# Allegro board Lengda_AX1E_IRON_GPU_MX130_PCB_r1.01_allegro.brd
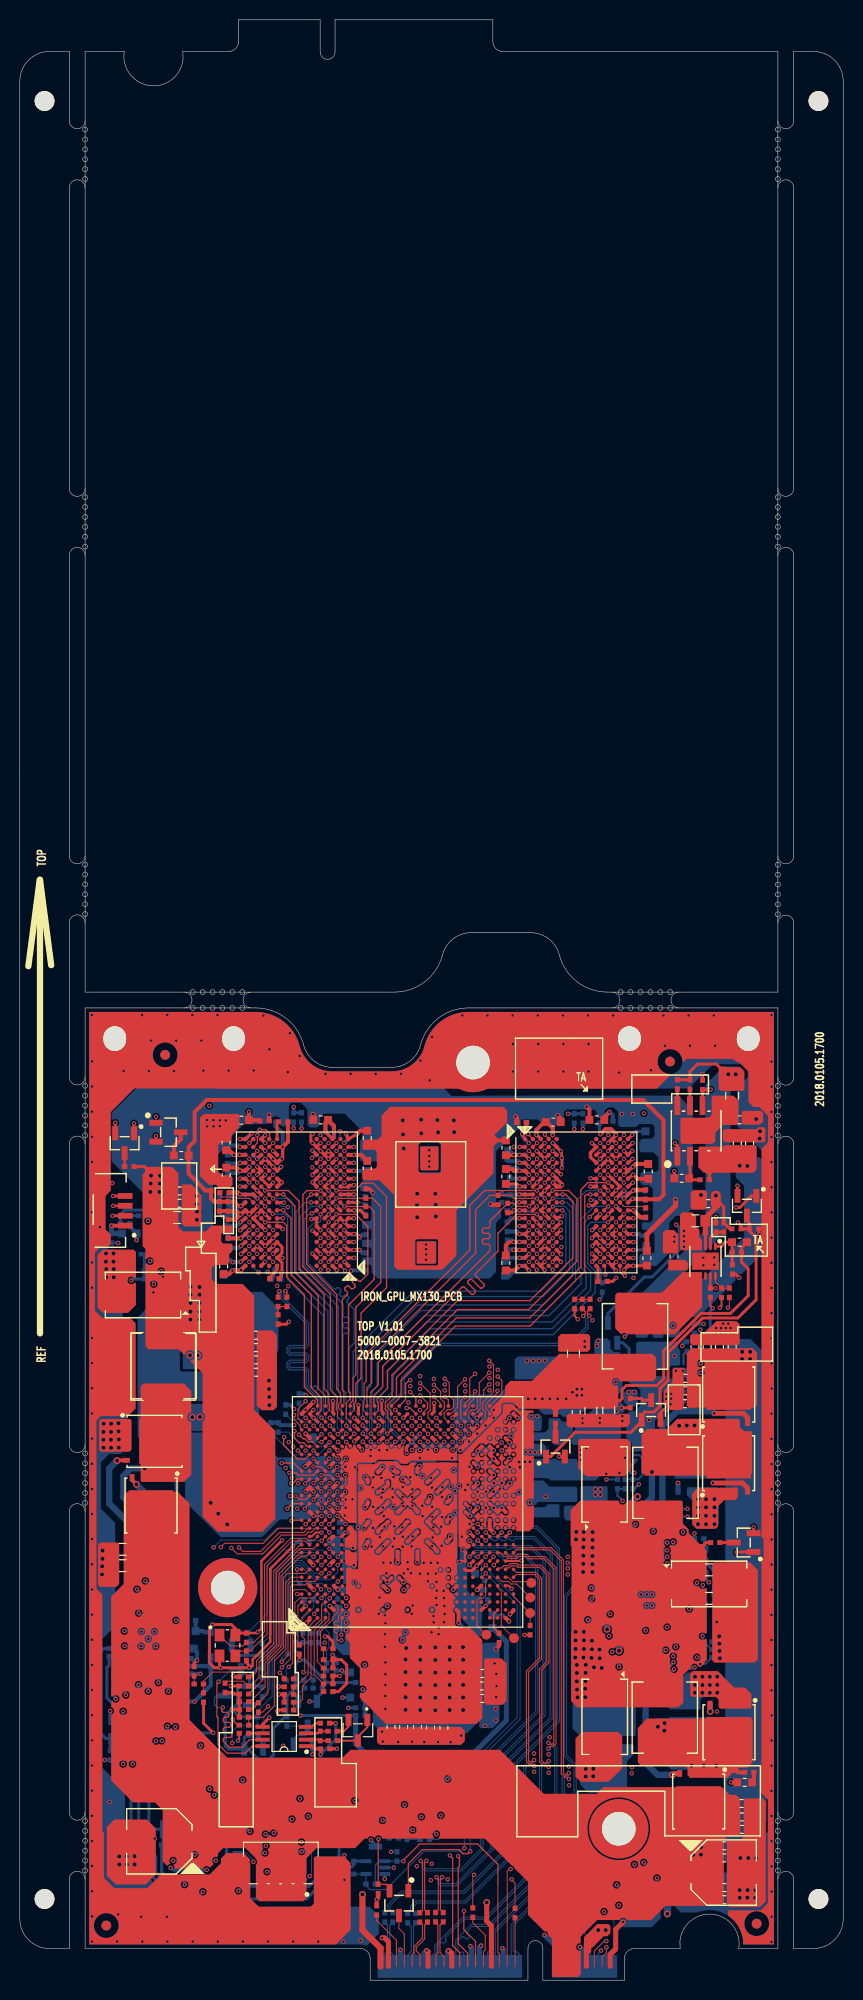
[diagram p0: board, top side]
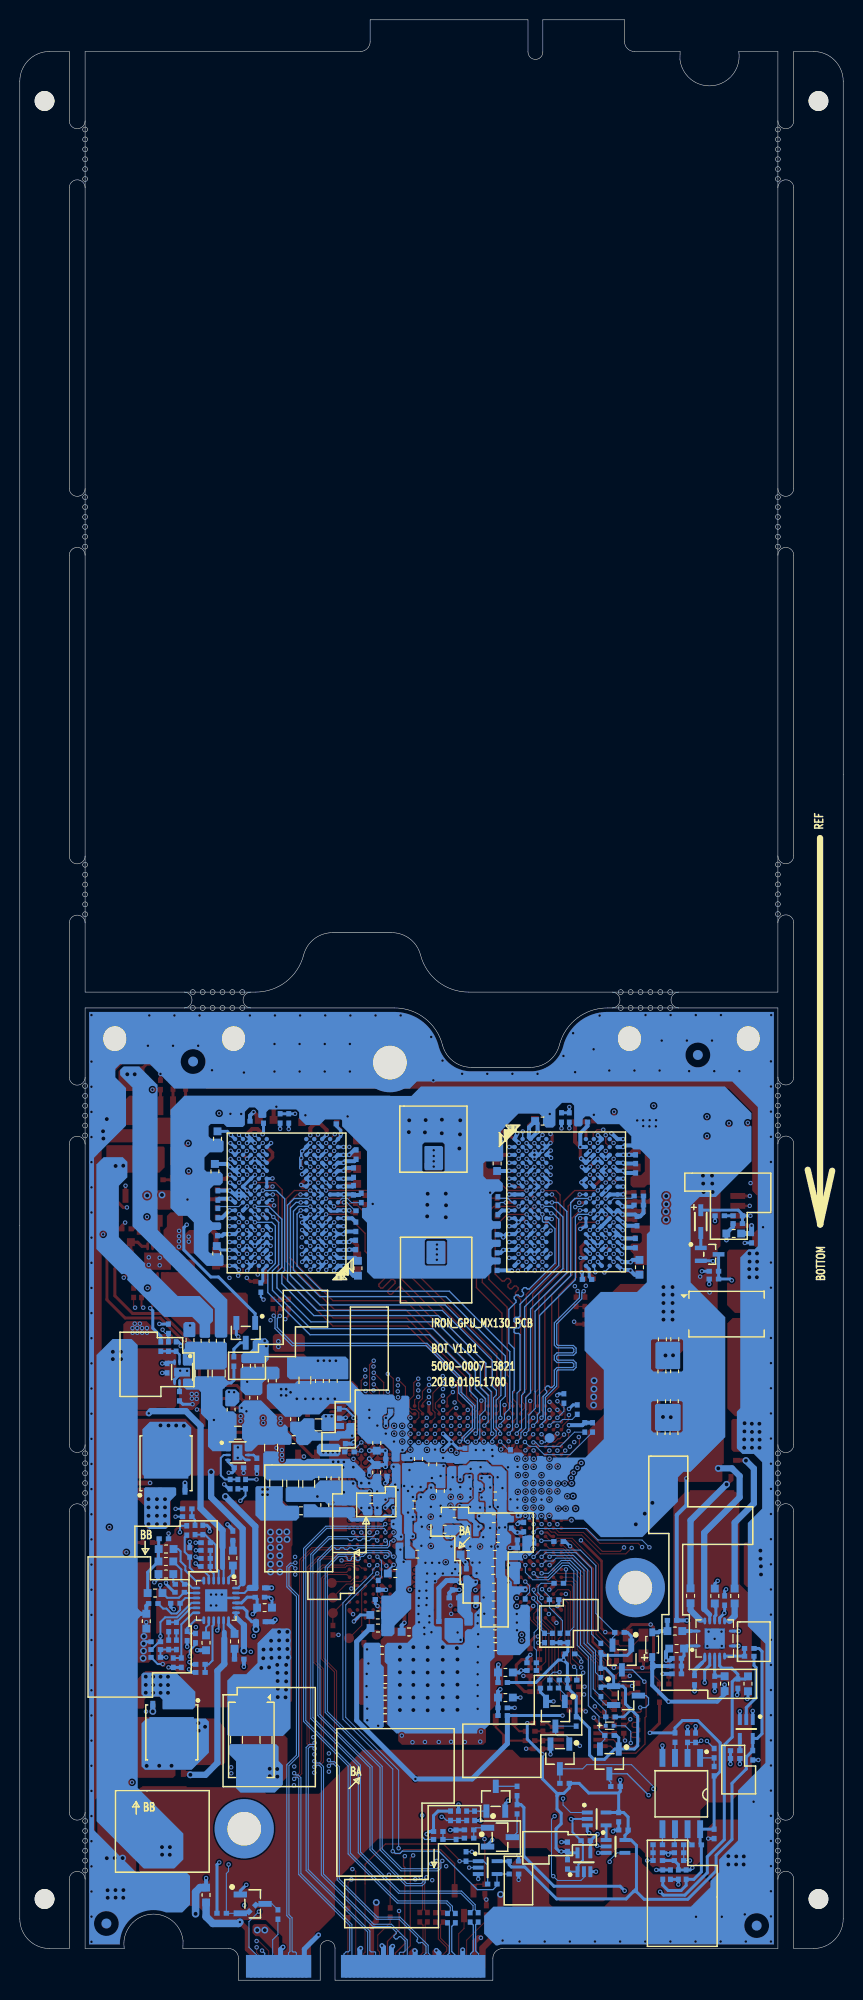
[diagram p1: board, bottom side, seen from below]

Outline 83.2 x 198 mm; copper layers: TOP, L2, L3, L4, L5, L6, L7, BOTTOM. Coordinates in mm from the lower left corner of the outline.

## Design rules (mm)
net group FBA_DQS<0>: nets FBA_DBI0 FBA_EDC0
net group FBA_DQS<1>: nets FBA_DBI1 FBA_EDC1
net group FBA_DQS<2>: nets FBA_DBI2 FBA_EDC2
net group FBA_DQS<3>: nets FBA_DBI3 FBA_EDC3
net group FBA_DQS<4>: nets FBA_DBI4 FBA_EDC4
net group FBA_DQS<5>: nets FBA_DBI5 FBA_EDC5
net group FBA_DQS<6>: nets FBA_DBI6 FBA_EDC6
net group FBA_DQS<7>: nets FBA_DBI7 FBA_EDC7
net group M_PCIE_TX3_GPU: nets PCIE_TXN3_GPU PCIE_TXP3_GPU
net group PCIE_RXN1_GPU: nets PCIE_RXN1_GPU PEX_TX0#
net group PCIE_RXN2_GPU: nets PCIE_RXN2_GPU PEX_TX1#
net group PCIE_RXN3_GPU: nets PCIE_RXN3_GPU PEX_TX2#
net group PCIE_RXN4_GPU: nets PCIE_RXN4_GPU PEX_TX3#
net group PCIE_RXP1_GPU: nets PCIE_RXP1_GPU PEX_TX0
net group PCIE_RXP2_GPU: nets PCIE_RXP2_GPU PEX_TX1
net group PCIE_RXP3_GPU: nets PCIE_RXP3_GPU PEX_TX2
net group PCIE_RXP4_GPU: nets PCIE_RXP4_GPU PEX_TX3
net group PEX_REFCLK: nets CLK_PCIE_GPU_N CLK_PCIE_GPU_P
net group PEX_RX0: nets PCIE_TXN1_GPU PCIE_TXP1_GPU
net group PEX_RX1: nets PCIE_TXN2_GPU PCIE_TXP4_GPU
net group FBA_DATA0: nets FBA_D0 FBA_D1 FBA_D2 FBA_D3 FBA_D4 FBA_D5 FBA_D6 FBA_D7
net group FBA_DATA1: nets FBA_D8 FBA_D9 FBA_D10 FBA_D11 FBA_D12 FBA_D13 FBA_D14 FBA_D15
net group FBA_DATA2: nets FBA_D16 FBA_D17 FBA_D18 FBA_D19 FBA_D20 FBA_D21 FBA_D22 FBA_D23
net group FBA_DATA3: nets FBA_D24 FBA_D25 FBA_D26 FBA_D27 FBA_D28 FBA_D29 FBA_D30 FBA_D31
net group FBA_DATA4: nets FBA_D32 FBA_D33 FBA_D34 FBA_D35 FBA_D36 FBA_D37 FBA_D38 FBA_D39
net group FBA_DATA5: nets FBA_D40 FBA_D41 FBA_D42 FBA_D43 FBA_D44 FBA_D45 FBA_D46 FBA_D47
net group FBA_DATA6: nets FBA_D48 FBA_D49 FBA_D50 FBA_D51 FBA_D52 FBA_D53 FBA_D54 FBA_D55
net group FBA_DATA7: nets FBA_D56 FBA_D57 FBA_D58 FBA_D59 FBA_D60 FBA_D61 FBA_D62 FBA_D63
net group M_PCIE_TX2_GPU: nets PCIE_TXP2_GPU
net group M_PCIE_TX4_GPU: nets PCIE_TXN4_GPU
net group NET_GND: nets GND
net group POWER: nets +V1P8S
nets with their own width: min track width 0.003; nets VDD_GPU_MAIN

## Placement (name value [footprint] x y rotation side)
C1  820pF  [CC0402N]  58.88 70.58 0 top
C2  1uF  [CC0402N]  49.63 47.76 90 bottom
C3  820pF  [CC0402N]  63.25 79.35 90 top
C4  820pF  [CC0402N]  25.89 70.78 0 bottom
C5  820pF  [CC0402N]  58.85 69.96 270 bottom
C6  820pF  [CC0402N]  20.66 78.29 180 bottom
C7  4.7uF  [CC0603N]  52.38 47.98 90 bottom
C8  0.01uF  [CC0402N]  56.06 68.29 270 top
C9  820pF  [CC0402N]  63.18 79.26 90 bottom
C10  100NF  [CC0402N]  50.41 47.75 90 bottom
C11  1uF  [CC0402N]  50.5 60.55 90 bottom
C12  10uF  [CC0603N]  73.74 84.53 90 top
C13  10uF  [CC0603N]  72.5 84.52 90 top
C14  1uF  [CC0402N]  45.74 52.64 0 bottom
C15  0.1u  [CC0402N]  71.5 84.47 90 top
C16  10uF  [CC0603N]  72.73 86.89 0 top
C17  0.1u  [CC0402N]  68.99 90.42 90 top
C18  100NF  [CC0402N]  30.86 23.38 0 top
C19  470pF  [CC0402N]  30.35 24.67 90 top
C20  1000pF  [CC0402N]  17.62 31.2 270 top
C21  100NF  [CC0402N]  33.27 12.02 0 bottom
C22  0.01uF  [CC0402N]  37.8 15.18 180 bottom
C23  0.01uF  [CC0402N]  37.25 16.61 90 bottom
C24  100NF  [CC0402N]  48.44 34.57 90 top
C275  1uF  [CC0402N]  46.21 57.48 180 bottom
C276  4.7uF  [CC0603N]  47.13 54.24 270 bottom
C298  4.7uF  [CC0603N]  56.22 57.39 270 top
C310  10UF  [CC0603N]  51.53 60.54 90 bottom
C322  10UF  [CC0603N]  52.93 60.51 90 bottom
C326  22uF  [CC0805N]  54.39 60.59 90 bottom
C327  22uF  [CC0805N]  55.94 63.28 90 top
C330  0.22uF  [CC0402N]  41.19 6.34 90 top
C331  0.22uF  [CC0402N]  40.42 6.34 90 top
C332  0.22uF  [CC0402N]  42.79 6.36 90 top
C333  0.22uF  [CC0402N]  42.01 6.36 90 top
C338  1uF  [CC0402N]  45.62 50.91 0 bottom
C342  1uF  [CC0402N]  44.46 46.37 180 bottom
C344  1uF  [CC0402N]  47.5 47.21 0 bottom
C370  1uF  [CC0402N]  45.61 48.84 270 bottom
C471  4.7uF  [CC0603N]  52.59 50.69 270 bottom
C472  4.7uF  [CC0603N]  51.34 50.69 270 bottom
C473  10UF  [CC0603N]  47.67 48.56 0 bottom
C474  10UF  [CC0603N]  47.14 51.28 90 bottom
C475  22uF  [CC0805N]  54.01 50.13 270 bottom
C476  22uF  [CC0805N]  55.62 50.16 270 bottom
C478  0.22uF  [CC0402N]  37.69 6.34 90 bottom
C532  0.22uF  [CC0402N]  36.88 6.34 90 bottom
C533  0.22uF  [CC0402N]  39.98 6.27 90 bottom
C534  0.22uF  [CC0402N]  39.19 6.27 90 bottom
C536  100NF  [CC0402N]  46.81 38.45 0 bottom
C537  4.7uF  [CC0603N]  47.03 36.89 0 bottom
C539  820pF  [CC0402N]  25.74 70.85 0 top
C540  820pF  [CC0402N]  26.62 86.7 0 top
C541  0.01uF  [CC0402N]  26.11 66.74 270 top
C542  820pF  [CC0402N]  21.04 78.15 270 top
C543  10uF  [CC0603N]  20.6 72.08 270 top
C553  1UF  [CC0402N]  42.25 73.49 180 bottom
C554  1UF  [CC0402N]  20.97 82.01 270 bottom
C555  1UF  [CC0402N]  20.98 83.84 270 bottom
C556  1UF  [CC0402N]  20.83 76.67 90 bottom
C557  100NF  [CC0402N]  21 74.45 90 bottom
C558  100NF  [CC0402N]  34.97 72.16 270 bottom
C559  100NF  [CC0402N]  26.31 86.68 180 bottom
C560  100NF  [CC0402N]  24.72 86.78 180 top
C561  100NF  [CC0402N]  58.57 87.03 270 bottom
C562  100NF  [CC0402N]  63.22 75.68 270 bottom
C567  100NF  [CC0402N]  50.3 55.96 0 bottom
C568  100NF  [CC0402N]  50.31 54.66 270 bottom
C569  22uF  [CC0805N]  53.02 56.09 180 bottom
C570  100NF  [CC0402N]  52.09 54.36 270 bottom
C571  100NF  [CC0402N]  51.28 54.35 270 bottom
C572  10uF  [CC0603N]  34.97 82.48 270 bottom
C573  1UF  [CC0402N]  42.23 74.27 180 top
C574  100NF  [CC0402N]  37.56 38.61 180 bottom
C575  1UF  [CC0402N]  21.05 76.35 90 top
C576  1UF  [CC0402N]  21.05 74.5 90 top
C577  1UF  [CC0402N]  42.23 73.5 180 top
C578  10uF  [CC0603N]  20.86 81.33 90 top
C579  1UF  [CC0402N]  49.48 81.57 90 bottom
C580  1UF  [CC0402N]  49.24 76.09 270 bottom
C581  1UF  [CC0402N]  49.26 74.26 270 bottom
C582  1UF  [CC0402N]  42.26 72.67 180 bottom
C583  100NF  [CC0402N]  34.96 73.94 270 bottom
C584  100NF  [CC0402N]  34.97 75.78 270 bottom
C585  100NF  [CC0402N]  42.23 72.71 180 top
C586  100NF  [CC0402N]  39.95 73.49 0 top
C587  100NF  [CC0402N]  39.95 74.3 0 top
C588  100NF  [CC0402N]  50.75 86.5 0 bottom
C596  10uF  [CC0603N]  20.84 84.59 270 top
C597  1UF  [CC0402N]  49.21 83.39 90 bottom
C598  1UF  [CC0402N]  40.06 72.66 0 bottom
C599  1UF  [CC0402N]  49.48 79.78 270 bottom
C600  1UF  [CC0402N]  42.23 74.29 180 bottom
C602  1UF  [CC0402N]  40.3 82.22 0 top
C603  1UF  [CC0402N]  33.91 47.82 0 bottom
C604  1UF  [CC0402N]  40.29 83.02 0 top
C605  10uF  [CC0603N]  30.38 86.77 0 bottom
C606  10uF  [CC0603N]  35.11 85.05 90 top
C607  22uF  [CC0603N]  18.27 64.73 270 bottom
C619  22uF  [CC0603N]  17.02 64.73 270 bottom
C620  100NF  [CC0402N]  38.22 53.26 90 bottom
C621  100NF  [CC0402N]  36.06 52.36 270 bottom
C622  1uF  [CC0603N]  35.11 82 90 top
C623  10uF  [CC0603N]  49.11 72.44 90 top
C624  1UF  [CC0402N]  33.97 50.28 0 bottom
C625  1UF  [CC0402N]  33.96 51.1 0 bottom
C628  1UF  [CC0402N]  35.25 51.98 270 bottom
C629  10uF  [CC0603N]  53.91 86.67 180 top
C630  10uF  [CC0603N]  49.12 84.08 90 top
C631  10uF  [CC0603N]  30.4 86.89 0 top
C632  22uF  [CC0603N]  42.91 52.64 270 bottom
C633  22uF  [CC0603N]  22.4 86.86 0 top
C634  100NF  [CC0402N]  37.23 52.58 270 bottom
C635  100NF  [CC0402N]  44.32 52.41 270 bottom
C636  1uF  [CC0603N]  20.59 72 270 bottom
C637  1UF  [CC0402N]  50.7 86.63 0 top
C638  1UF  [CC0402N]  40.28 83.85 0 top
C647  1UF  [CC0402N]  42.44 83.84 180 top
C670  10uF  [CC0603N]  41.47 52.1 270 bottom
C672  10uF  [CC0603N]  23.86 65.14 180 top
C681  10uF  [CC0603N]  58.3 86.89 0 top
C682  22uF  [CC0603N]  63.5 81.69 90 top
C683  22uF  [CC0603N]  63.37 72.93 270 top
C684  100NF  [CC0402N]  60.41 86.75 180 bottom
C691  100NF  [CC0402N]  42.45 83.05 180 top
C692  1uF  [CC0603N]  63.3 73.4 90 bottom
C707  1UF  [CC0402N]  39.94 72.7 0 top
C710  1UF  [CC0402N]  42.48 82.26 180 top
C715  1UF  [CC0402N]  23.77 59.52 0 top
C726  10uF  [CC0603N]  23.87 63.89 0 top
C729  10uF  [CC0603N]  23.87 62.65 0 top
C739  0.1uF  [CC0603N]  68.22 63.97 90 top
C741  22uF  [CC0603N]  63.48 81.69 90 bottom
C742  22uF  [CC0603N]  63.22 84.98 90 bottom
C743  100NF  [CC0402N]  23.78 58.72 0 top
C744  100NF  [CC0402N]  23.78 60.3 0 top
C745  1uF  [CC0603N]  49.03 71.91 270 bottom
C748  10uF  [CC0603N]  49.11 81.18 270 top
C749  1UF  [CC0402N]  37.15 44.84 90 bottom
C758  10uF  [CC0603N]  38.78 25.56 270 top
C759  10uF  [CC0603N]  40.19 25.57 270 top
C761  10uF  [CC0603N]  41.51 25.52 270 top
C764  10uF  [CC0603N]  46.27 30.36 0 bottom
C765  1UF  [CC0402N]  39.05 51.52 180 bottom
C766  1UF  [CC0402N]  40.28 82.18 0 bottom
C769  1UF  [CC0402N]  42.42 83.8 180 bottom
C783  1UF  [CC0402N]  42.44 82.99 180 bottom
C789  1UF  [CC0402N]  40.06 73.45 0 bottom
C804  22uF  [CC0805N]  58.32 24.27 270 bottom
C805  22uF  [CC0805N]  61.3 24.28 270 bottom
C809  22uF  [CC0603N]  39.27 47.11 180 bottom
C810  10uF  [CC0603N]  34.89 44.62 180 bottom
C811  10uF  [CC0603N]  18.35 58.47 270 bottom
C812  10uF  [CC0603N]  18.32 61.49 90 bottom
C813  22uF  [CC0603N]  17.06 58.48 270 bottom
C814  22uF  [CC0603N]  17.04 61.49 90 bottom
C815  10uF  [CC0603N]  35.15 33.69 180 bottom
C816  10uF  [CC0603N]  35.21 36.28 180 bottom
C817  10uF  [CC0603N]  35.2 34.98 180 bottom
C818  10uF  [CC0603N]  46.29 29.12 0 bottom
C819  10uF  [CC0603N]  46.29 27.88 0 bottom
C820  10uF  [CC0603N]  37.92 43 0 bottom
C821  1UF  [CC0402N]  40.29 82.99 0 bottom
C822  1UF  [CC0402N]  40.26 83.83 0 bottom
C823  1UF  [CC0402N]  42.45 82.14 180 bottom
C824  1UF  [CC0402N]  40.06 74.25 0 bottom
C825  10uF  [CC0603N]  18.39 55.25 90 bottom
C826  22uF  [CC0603N]  17.1 55.25 90 bottom
C827  1UF  [CC0402N]  43.57 45.57 0 bottom
C828  1UF  [CC0402N]  43.54 44.18 0 bottom
C829  1UF  [CC0402N]  37.54 50.1 180 bottom
C830  1UF  [CC0402N]  43.88 25.69 270 top
C831  10uF  [CC0603N]  43.87 35.18 0 bottom
C832  1UF  [CC0402N]  46.75 32 0 top
C833  10uF  [CC0603N]  43.35 48.01 0 bottom
C834  10uF  [CC0603N]  43.03 43.03 0 bottom
C835  10uF  [CC0603N]  40.7 49.42 90 bottom
C836  10uF  [CC0603N]  46.69 29.71 0 top
C837  10uF  [CC0603N]  46.7 28.46 0 top
C838  10uF  [CC0603N]  35.16 48.91 180 bottom
C839  10uF  [CC0603N]  35.21 43 180 bottom
C840  10uF  [CC0603N]  46.7 30.98 0 top
C841  10uF  [CC0603N]  46.3 26.51 0 bottom
C842  10uF  [CC0603N]  40.28 45.55 180 bottom
C843  10uF  [CC0603N]  35.32 37.91 180 bottom
C844  10uF  [CC0603N]  35.29 39.69 180 bottom
C845  10uF  [CC0603N]  35.36 41.39 180 bottom
C846  22uF  [CC0603N]  37.51 25.59 270 top
C847  22uF  [CC0603N]  42.86 25.5 270 top
C848  22uF  [CC0603N]  46.6 33.32 0 bottom
C849  100NF  [CC0402N]  33.01 39.82 270 bottom
C850  100NF  [CC0402N]  32.97 42.37 90 bottom
C851  1uF  [CC0402N]  34.41 27.51 180 bottom
C852  4.7uF  [CC0603N]  34.13 28.55 180 bottom
C853  22uF  [CC0805N]  69.62 38.56 0 top
C854  22uF  [CC0805N]  69.63 41.44 0 top
C855  100NF  [CC0402N]  32.44 43.66 180 bottom
C856  1uF  [CC0402N]  32.44 44.47 180 bottom
C857  4.7uF  [CC0603N]  34.13 31.08 180 bottom
C858  100NF  [CC0402N]  39.33 38.62 0 bottom
C859  100NF  [CC0402N]  38.08 41.08 90 bottom
C860  22uF  [CC0603N]  60.29 62.05 90 bottom
C861  4.7uF  [CC0603N]  59.02 62.06 90 bottom
C862  100NF  [CC0402N]  33.54 46.14 90 bottom
C863  100NF  [CC0402N]  13.04 14.78 270 bottom
C864  27pF  [CC0402N]  22.89 34.59 90 top
C865  27pF  [CC0402N]  22.9 32.77 270 top
C866  100NF  [CC0402N]  39.5 39.9 270 bottom
C867  100NF  [CC0402N]  36.21 9.22 90 top
C868  4.7UF  [CC0603N]  69.45 63.96 90 top
C869  4.7UF  [CC0603N]  70.7 63.98 90 top
C870  4.7UF  [CC0603N]  67.25 59.52 180 top
C871  4.7UF  [CC0603N]  67.23 58.23 180 top
C872  4.7UF  [CC0603N]  71.98 63.98 90 top
C873  4.7UF  [CC0603N]  67.26 60.79 180 top
C874  1uF  [CC0402N]  58.94 38.68 180 bottom
C875  4.7uF  [CC0603N]  58.47 37.63 180 bottom
C876  0.1uF  [CC0603N]  35.31 46.61 180 bottom
C877  100NF  [CC0402N]  61.67 44.88 90 bottom
C878  100NF  [CC0402N]  64.41 44.19 180 bottom
C879  1uF  [CC0402N]  67.04 39.18 180 bottom
C880  100NF  [CC0402N]  61.03 32.43 180 bottom
C881  0.1uF  [CC0603N]  72.93 17.85 0 top
C882  4.7UF  [CC0603N]  72.96 15.23 0 top
C883  4.7UF  [CC0603N]  72.96 16.49 0 top
C884  4.7UF  [CC0603N]  71.19 13.57 0 top
C885  4.7UF  [CC0603N]  71.19 12.35 0 top
C886  4.7UF  [CC0603N]  71.2 9.35 0 top
C887  4.7UF  [CC0603N]  71.2 8.13 0 top
C888  100NF  [CC0402N]  66.03 43.22 90 bottom
C889  1.0 nF  [CC0402N]  73.7 21 0 top
C890  4700pF  [CC0402N]  68.64 44.59 180 bottom
C891  47pF  [CC0402N]  67.69 32.07 270 bottom
C892  1.0 nF  [CC0402N]  67.37 33.87 270 bottom
C893  1.0 nF  [CC0402N]  69.46 33.4 180 bottom
C894  100NF  [CC0402N]  17.29 36.34 0 bottom
C896  10uF  [CC0805N]  10.39 41.87 180 top
C898  10uF  [CC0805N]  10.39 43.52 180 top
C899  0.1uF  [CC0603N]  16.83 33.49 0 bottom
C900  1UF  [CC0402N]  11.98 38.35 270 bottom
C901  10UF  [CC0603N]  23.87 61.41 0 top
C903  10UF  [CC0603N]  16.14 78.47 0 top
C904  22uF  [CC0805N]  15.88 77.03 0 top
C909  0.1uF  [CC0603N]  16.14 79.71 0 top
C910  1UF  [CC0402N]  12.99 30.23 90 bottom
C911  2.2uF  [CC0603N]  66 64.65 90 bottom
C912  2.2uF  [CC0603N]  61.85 57.63 90 bottom
C913  1.0 nF  [CC0402N]  67.06 58.98 90 bottom
C914  1.0 nF  [CC0402N]  59.25 52.24 90 bottom
C915  100NF  [CC0402N]  61.06 51.76 0 bottom
C916  100NF  [CC0402N]  68.32 61.82 90 bottom
C917  100NF  [CC0402N]  67.41 64 90 bottom
C918  100NF  [CC0402N]  61.94 50.1 270 bottom
C919  470PF  [CC0402N]  67.16 71.64 90 top
C920  100NF  [CC0402N]  68.8 75.5 180 top
C921  22uF  [CC0805N]  68.27 76.7 180 top
C922  100NF  [CC0402N]  70.9 69.43 270 top
C923  22uF  [CC0805N]  59.51 57.55 270 top
C924  22uF  [CC0805N]  57.71 57.53 270 top
C925  100NF  [CC0402N]  54.69 63.36 90 top
C926  33NF  [CC0603N]  72.72 74.54 180 top
C927  100NF  [CC0402N]  22.69 16.46 270 bottom
C928  100NF  [CC0402N]  22.21 15.17 0 bottom
C929  1uF  [CC0402N]  70.35 76.03 90 top
C930  100NF  [CC0402N]  27.86 13.47 90 bottom
C931  100NF  [CC0402N]  74.2 75.89 0 top
C932  100NF  [CC0402N]  9.14 22.72 270 bottom
C933  100NF  [CC0402N]  10.92 22.4 180 bottom
CP1  330uF  [CCP7343N]  11.79 67.28 180 bottom
CP3  330uF  [CCP7343N]  59.81 24.27 270 bottom
CP4  330uF  [CCP7343N]  69.65 40.02 0 top
CP10  330uF  [CCP7343N]  59.09 50.07 90 top
CP11  330uF  [CCP7343N]  59.11 26.6 270 top
CP12  47uF  [CAE660W800HN]  71.13 10.86 0 top
CP13  330uF  [CCP7343N]  12.45 69.21 180 top
D9  RB521CM-30  [SOD1006BN]  23.6 25.7 180 bottom
D12  BAT54WS-7-F  [SOD1713N]  19.3 33.89 90 bottom
FB1  120  [FB0603N]  55.43 56.66 90 bottom
FB2  120  [FB0603N]  57.69 60.57 90 bottom
FB27  120  [FB0603N]  55.54 54.6 0 bottom
FB28  120  [FB0603N]  59.57 58.82 90 bottom
GC1  1uF  [CC0603N]  70.42 36.26 270 bottom
GC2  100pF  [CC0402N]  67.48 38.07 180 bottom
GC3  1uF  [CC0402N]  64.95 31.09 180 bottom
GC315  0.1u  [CC0402N]  13.07 71.6 180 bottom
GC316  1000pF  [CC0402N]  12.48 77.21 0 bottom
GC317  0.1u  [CC0402N]  9.26 74.94 90 bottom
GCN1  PCIE-FINGER  [FINGER-PCIE-80P-52N]  52.1 1.4 0 bottom
GCN2  1.25T-2-4PWB  [SMD-CN-125P-4BN]  26.37 10.99 0 top
GCN9  WB1012US-04T5  [SMD-CN-100P-4N-V-CB]  8.1 77.71 270 top
GD10  1SS355TE17  [SOD2514N]  14.39 76.62 90 bottom
GFB11  180  [FB0603N]  11.06 75.42 0 bottom
GQ2  DTC144EUA  [SOT65P210-3N]  13.49 73.31 180 bottom
GR1  499k  [RC0402N]  69.71 38.04 0 bottom
GR2  0  [RC0603N]  64.38 8.6 270 bottom
GR3  0  [RC0402N]  64.95 31.9 180 bottom
GR4  30k  [RC0603N]  64.38 34.08 90 bottom
GR5  0  [RC0402N]  57.12 6.63 90 bottom
GR6  2.2K  [RC0402N]  65.45 34.55 90 bottom
GR8  0  [RC0402N]  50.03 6.78 90 top
GR9  0  [RC0402N]  66.29 34.77 270 bottom
GR11  0  [RC0402N]  45.77 6.83 90 top
GR13  0  [RC0402N]  36.06 7.05 90 top
GR427  10k  [RC0402N]  13.07 70.82 180 bottom
GR428  10k  [RC0402N]  10.65 76.42 180 bottom
GR429  100  [RC0402N]  10.65 77.21 180 bottom
GU1  RT8813A/D  [QFN50P400X400-24AN]  63.36 38.36 270 bottom
L1  0.36uH  [LC7266N]  65.2 50.23 0 top
L8  0.36uH  [LC7266N]  65.21 26.52 180 top
L9  1.5uH  [L600P-686X647-2N]  14.5 61.99 90 top
L10  2.2uH  [LC6666N]  14.54 62.02 90 top
L11  0.47uH  [LC6666N]  62.16 65.04 270 top
M1  K4G41325FC  [BGA80P14X17-170N-A]  28 78.56 180 top
M2  K4G41325FC  [BGA80P14X17-170N-A]  56.25 78.56 0 top
M3  K4G41325FC  [BGA80P14X17-170N-A]  28 78.56 180 bottom
M4  K4G41325FC  [BGA80P14X17-170N-A]  56.25 78.56 0 bottom
MARK1  MARK  [MARK-D100D250]  8.74 5.51 180 bottom
MARK2  MARK  [MARK-D100D250]  8.74 5.52 0 top
MARK3  MARK  [MARK-D100D250]  74.46 5.7 0 top
MARK4  MARK  [MARK-D100D250]  74.45 5.73 180 bottom
MARK5  MARK  [MARK-D100D250]  65.69 92.79 180 bottom
MARK6  MARK  [MARK-D100D250]  65.7 92.79 0 top
MARK7  MARK  [MARK-D100D250]  14.69 93.45 180 bottom
MARK8  MARK  [MARK-D100D250]  14.69 93.46 0 top
MH1  H  [MTG230H500]  9.6 95.2 0 top
MH2  H  [MTG230H500]  21.6 95.2 0 top
MH3  H  [MTG230H500]  61.6 95.2 0 top
MH4  H  [MTG230H500]  73.6 95.2 0 top
MH5  H  [MTG340H600]  60.53 15.3 0 top
MH6  H  [MTG340H600]  21.01 39.65 0 top
MH7  H  [MTG340H600]  45.8 92.68 0 top
MH8  H  [MTG230H500]  9.6 95 0 top
MH9  H  [MTG230H500]  21.6 95 0 top
MH10  H  [MTG230H500]  61.6 95 0 top
MH11  H  [MTG230H500]  73.6 95 0 top
NOREF  -  [unnamed]  2.5 8.2 0 top
NOREF#2  -  [unnamed]  80.7 189.8 0 top
NOREF#3  -  [unnamed]  2.5 189.8 0 top
NOREF#4  -  [unnamed]  80.7 8.2 0 top
PCP3  47uF  [CAE660W800HN]  14.1 14.03 180 top
Q1  MMBT3904  [SOT95P230-3N]  34.16 25.24 270 top
Q2  BSS138-7-F  [SOT95P280-3N]  35.1 18.33 90 bottom
Q4  BSS138-7-F  [SOT95P280-3N]  34.68 14.45 180 bottom
Q6  BSS138-7-F  [SOT95P280-3N]  59.67 7.71 180 bottom
Q7  BSS138-7-F  [SOT95P280-3N]  15.02 85.64 0 top
Q25  BSS138-7-F  [SOT95P280-3N]  28.63 22.6 270 bottom
Q30  BSS138-7-F  [SOT95P280-3N]  29.08 26.91 270 bottom
Q33  BSS138-7-F  [SOT95P280-3N]  38.31 7.78 270 top
Q34  BSS138-7-F  [SOT95P280-3N]  22.36 32.59 270 bottom
Q35  BSS138-7-F  [SOT95P280-3N]  21.95 28.75 180 bottom
Q36  BSS138-7-F  [SOT95P280-3N]  23.63 22.1 270 bottom
Q37  SM4370NSKPC-TRG  [SOIC127P605X520-8N]  71.64 59.15 90 top
Q38  SM4373NS-KPCTRG  [SOIC127P605X520-8N]  71.63 52.22 90 top
Q39  SM4373NS-KPCTRG  [SOIC127P605X520-8N]  68.41 52.2 90 bottom
Q40  SM4370NSKPC-TRG  [SOIC127P605X520-8N]  68.58 18.05 270 top
Q41  SM4373NS-KPCTRG  [SOIC127P605X520-8N]  71.65 25.05 270 top
Q42  SM4373NS-KPCTRG  [SOIC127P605X520-8N]  67.86 25.04 270 bottom
Q44  SM4370NSKPC-TRG  [SOIC127P605X520-8N]  13.25 47.95 270 top
Q54  SM4373NS-KPCTRG  [SOIC127P605X520-8N]  13.6 54.41 0 top
Q55  2N7002-7-F  [SOT95P240-3N]  60.37 65.38 270 bottom
Q70  2N7002-7-F  [SOT95P240-3N]  73.15 44.2 180 top
Q71  2N7002-7-F  [SOT95P240-3N]  54.13 53.89 90 top
Q72  2N7002-7-F  [SOT95P240-3N]  10.59 84.53 270 top
Q75  2N7002-7-F  [SOT95P240-3N]  63.79 57.59 90 top
Q76  2N7002-7-F  [SOT95P240-3N]  73.47 78.22 270 top
R1  1k  [RC0402N]  48.75 77.72 180 bottom
R2  0  [RC0805N]  57.81 53.79 90 bottom
R3  0  [RC0805N]  57.29 50.2 270 bottom
R4  121  [RC0402N]  63.25 77.54 90 top
R5  1k  [RC0402N]  56.03 87.04 270 bottom
R6  1k  [RC0402N]  34.89 79.6 90 bottom
R7  1k  [RC0402N]  48.7 79.01 270 bottom
R8  0  [RC0603N]  45.26 41.08 0 bottom
R9  121  [RC0402N]  20.65 79.2 0 bottom
R10  1k  [RC0402N]  28.47 87.13 270 bottom
R11  0  [RC0603N]  54.78 47.41 180 bottom
R12  200  [RC0402N]  49.89 53.36 0 bottom
R13  40.2  [RC0402N]  56.85 68.29 90 top
R14  40.2  [RC0402N]  57.63 68.29 270 top
R15  40.2K  [RC0402N]  32.13 38.03 270 bottom
R16  100K  [RC0402N]  67.72 90.47 270 top
R17  100K  [RC0402N]  66.45 90.47 90 top
R18  121  [RC0402N]  63.18 77.48 90 bottom
R19  1k  [RC0402N]  56.9 87.04 270 bottom
R20  0  [RC0603N]  62.94 64.59 270 bottom
R21  20K  [RC0402N]  69.2 80.85 0 top
R22  0 ohm  [RC0805N]  71.98 89.33 90 top
R23  16k  [RC0603N]  66.88 80.99 0 top
R24  0  [RC0402N]  31.64 24.19 0 top
R25  0  [RC0402N]  31.62 25.14 0 top
R26  4.7K  [RC0402N]  22.65 24.94 0 top
R27  4.7K  [RC0402N]  30.83 25.96 0 top
R28  10k  [RC0402N]  18.57 28.55 270 top
R29  10k  [RC0402N]  18.09 29.92 0 top
R30  0  [RC0402N]  38.11 12.5 270 bottom
R31  0  [RC0402N]  35.45 9.71 180 bottom
R32  100k  [RC0402N]  33.27 10.72 180 bottom
R33  0  [RC0402N]  27.19 30.45 180 top
R34  0  [RC0402N]  30.18 34.56 270 bottom
R35  0  [RC0402N]  24.12 27.54 90 top
R36  0  [RC0402N]  28.74 40.09 180 bottom
R37  10k  [RC0402N]  40.92 15.02 180 bottom
R38  48.7k  [RC0402N]  32.96 17.27 90 bottom
R39  1k  [RC0402N]  37.8 14.35 180 bottom
R40  10k  [RC0402N]  39.12 14.69 90 bottom
R41  10k  [RC0402N]  39.67 16.61 270 bottom
R42  24.9k  [RC0402N]  32.96 19.11 270 bottom
R43  1k  [RC0402N]  38.05 16.61 90 bottom
R44  10k  [RC0402N]  38.88 16.61 90 bottom
R45  0  [RC0402N]  40.92 14.22 180 bottom
R100  10k  [RC0402N]  62.8 6.76 180 bottom
R153  0  [RC0402N]  59.71 7.25 135 bottom
R154  0  [RC0603N]  47.01 35.57 0 bottom
R171  2.49K  [RC0402N]  50.92 57.23 90 bottom
R176  40.2  [RC0402N]  26.99 68.51 270 top
R177  40.2  [RC0402N]  26.1 68.52 90 top
R178  549  [RC0402N]  19.33 80.23 270 top
R179  931  [RC0603N]  16.31 83.29 180 top
R180  1.33k  [RC0402N]  20.17 78.16 90 top
R181  121  [RC0402N]  20.69 79.56 180 top
R187  1k  [RC0402N]  27.67 87.13 270 bottom
R194  60.4  [RC0402N]  25.33 55.83 90 bottom
R197  60.4  [RC0402N]  33.62 53.1 270 bottom
R198  100k  [RC0402N]  29.21 38.44 0 bottom
R200  10k  [RC0402N]  34.98 79.46 90 top
R201  10k  [RC0402N]  48.33 78.8 270 top
R240  10k  [RC0402N]  34.97 77.67 90 top
R241  10k  [RC0402N]  49.29 77.99 90 top
R246  40.2  [RC0402N]  26.11 55.83 270 bottom
R247  40.2  [RC0402N]  26.87 57.63 270 bottom
R248  60.4  [RC0402N]  28.22 58.75 270 bottom
R250  0  [RC0402N]  34.41 26.73 180 bottom
R251  0  [RC0402N]  34.41 30.07 180 bottom
R252  0  [RC0402N]  38.47 36.23 180 bottom
R257  49.9k  [RC0402N]  20.75 29.52 270 top
R259  0  [RC0402N]  32.28 45.76 270 bottom
R391  10k  [RC0402N]  22.64 30.63 0 top
R392  10k  [RC0402N]  22.64 29.72 180 top
R479  4.7K  [RC0402N]  17 24.5 90 bottom
R480  4.7K  [RC0402N]  13.04 21.11 270 bottom
R481  4.7K  [RC0402N]  14.81 13.67 180 bottom
R482  0  [RC0402N]  40.38 36.22 0 bottom
R483  33  [RC0402N]  13.04 22.93 270 bottom
R485  45.3k  [RC0402N]  31.17 29.15 0 top
R486  100k  [RC0402N]  31.17 31.53 0 top
R505  100k  [RC0402N]  31.48 32.06 0 bottom
R507  100k  [RC0402N]  31.17 32.38 0 top
R514  100k  [RC0402N]  27.19 28.07 180 top
R515  100k  [RC0402N]  27.19 28.86 180 top
R516  100  [RC0402N]  18.74 13.68 180 bottom
R517  100  [RC0402N]  16.59 13.68 0 bottom
R528  100k  [RC0402N]  31.17 29.93 180 top
R532  100k  [RC0402N]  31.17 30.73 180 top
R533  100k  [RC0402N]  31.48 31.28 180 bottom
R556  100k  [RC0402N]  31.17 33.48 180 top
R566  100k  [RC0402N]  27.19 27.29 0 top
R570  100k  [RC0402N]  27.19 29.64 0 top
R587  10k  [RC0402N]  28.76 44.31 0 bottom
R588  100k  [RC0402N]  18.74 12.08 180 bottom
R589  100k  [RC0402N]  14.91 24.49 90 bottom
R592  100k  [RC0402N]  16.59 12.08 0 bottom
R593  0  [RC0402N]  15.87 10.66 90 bottom
R594  0  [RC0402N]  16.66 10.66 90 bottom
R595  45.3k  [RC0402N]  18.74 12.87 0 bottom
R596  4.99k  [RC0402N]  15.73 24.49 270 bottom
R597  4.99k  [RC0402N]  16.59 12.87 180 bottom
R598  0  [RC0402N]  18.23 10.66 90 bottom
R599  0  [RC0402N]  17.46 10.66 90 bottom
R600  10k  [RC0402N]  28.15 19.88 0 bottom
R601  100k  [RC0402N]  26.98 26.13 90 bottom
R602  10k  [RC0402N]  28.29 29.51 0 bottom
R603  1k  [RC0402N]  29.17 30.32 180 bottom
R604  10k  [RC0402N]  30.12 29.49 180 bottom
R605  10k  [RC0402N]  51.56 35.35 270 top
R606  10k  [RC0402N]  46.98 39.9 270 bottom
R614  2.2K  [RC0402N]  22.61 35.13 0 bottom
R615  2.2K  [RC0402N]  24.48 29.11 270 bottom
R617  10k  [RC0402N]  22.66 26.55 0 top
R618  0  [RC0402N]  22.66 25.76 0 top
R619  2.2K  [RC0402N]  22.66 28.9 180 top
R622  2.2K  [RC0402N]  22.66 28.13 180 top
R631  2.2K  [RC0402N]  24.49 31.03 90 bottom
R634  10k  [RC0402N]  27.83 34.57 90 bottom
R635  10k  [RC0402N]  27.6 32.96 180 bottom
R636  10k  [RC0402N]  27.39 30.31 180 bottom
R637  10k  [RC0402N]  60.39 50.1 270 bottom
R638  10k  [RC0402N]  28.61 34.56 90 bottom
R639  10k  [RC0402N]  29.39 34.56 90 bottom
R640  10k  [RC0402N]  28.26 33.4 90 top
R641  2.2K  [RC0402N]  24.49 33.55 270 bottom
R642  100k  [RC0402N]  23.51 26.6 0 bottom
R643  10k  [RC0402N]  22.66 27.34 0 top
R644  10k  [RC0402N]  23.01 19.56 0 bottom
R645  10k  [RC0402N]  23.61 24.72 0 bottom
R646  0  [RC0603N]  61.67 42.63 270 bottom
R647  10k  [RC0402N]  64.42 42.6 180 bottom
R648  0  [RC0402N]  64.42 43.42 180 bottom
R649  0  [RC0402N]  64.42 41.79 180 bottom
R650  2.2K  [RC0402N]  58.93 39.62 180 bottom
R651  0  [RC0402N]  66.33 45.42 270 bottom
R652  0  [RC0603N]  61.51 34.23 90 bottom
R654  4.32K  [RC0603N]  68.44 42.29 180 bottom
R655  20.5K  [RC0603N]  69.53 39.1 0 bottom
R656  6.19K  [RC0603N]  68.41 43.55 0 bottom
R657  15.8k  [RC0402N]  67.02 39.99 0 bottom
R658  1k  [RC0603N]  68.44 41.02 0 bottom
R659  2.2K  [RC0402N]  58.86 36.21 180 bottom
R661  1  [RC0603N]  73.25 19.98 0 top
R664  27K  [RC0402N]  66.88 32.07 270 bottom
R665  100  [RC0402N]  69.46 34.18 0 bottom
R666  40.2  [RC0402N]  67.37 35.67 270 bottom
R670  0  [RC0402N]  68.16 35.67 270 bottom
R676  0  [RC0402N]  68.16 33.87 270 bottom
R677  100  [RC0402N]  69.46 32.61 0 bottom
R679  10k  [RC0402N]  16.82 31.73 180 bottom
R687  0  [RC0402N]  16.82 30.94 180 bottom
R688  100k  [RC0402N]  16.82 32.5 0 bottom
R691  2.2  [RC0603N]  17.01 35.26 0 bottom
R695  220K  [RC0402N]  15.02 30.31 270 bottom
R696  2.2  [RC0603N]  11.98 29.95 270 bottom
R697  10k  [RC0402N]  9.49 33.51 0 bottom
R698  0  [RC0603N]  15.42 38.83 90 bottom
R699  15K  [RC0603N]  12.97 38.8 90 bottom
R700  0  [RC0402N]  9.49 32.72 0 bottom
R701  0  [RC0603N]  10.97 38.8 90 bottom
R702  12K  [RC0603N]  9.62 29.94 90 bottom
R703  15K  [RC0402N]  10.65 29.95 270 bottom
R704  0  [RC0805N]  64.83 61.27 270 bottom
R705  0  [RC0805N]  63.1 61.27 270 bottom
R706  0  [RC0805N]  61.16 55.29 180 bottom
R712  0  [RC0603N]  64.48 64.57 270 bottom
R734  10k  [RC0402N]  68.95 64 270 bottom
R735  0  [RC0603N]  69.58 78.43 0 top
R736  0  [RC0402N]  61.17 50.1 270 bottom
R737  0  [RC0402N]  68.18 64 90 bottom
R738  10k  [RC0402N]  68.18 65.79 90 bottom
R739  10k  [RC0402N]  66.29 46.82 180 bottom
R740  10k  [RC0402N]  69.78 69.43 90 top
R741  1  [RC0603N]  66.1 73.11 90 top
R742  0  [RC0402N]  66.29 47.6 0 bottom
R743  10k  [RC0402N]  65.49 45.48 270 bottom
R744  200K  [RC0402N]  64.71 45.48 270 bottom
R745  1k  [RC0402N]  71.7 69.43 90 top
R746  30K  [RC0402N]  72.45 73.54 180 top
R747  10  [RC0402N]  71.13 76.03 270 top
R748  120K  [RC0402N]  72.01 71.78 270 top
R749  10k  [RC0402N]  27.86 11.7 270 bottom
R750  680  [RC0402N]  61.57 62.49 90 bottom
R751  680  [RC0402N]  70.26 44.2 0 top
R752  680  [RC0402N]  54.13 56.69 270 top
R753  680  [RC0402N]  11.07 82.17 180 top
R754  680  [RC0402N]  61.68 58.29 90 top
R755  100k  [RC0402N]  72.42 75.89 180 top
R756  0  [RC0402N]  26.02 14.09 180 bottom
R757  10k  [RC0402N]  10.92 23.18 0 bottom
R1722  1k  [RC0402N]  34.89 77.81 90 bottom
TP1  TP  [TEST100]  29.66 54.76 270 bottom
TP9  TP  [TEST100]  49.94 34.54 270 top
TP15  TP  [TEST100]  51.58 38.65 270 top
TP19  TP  [TEST100]  51.68 40.13 270 top
TP24  TP  [TEST100]  47.14 34.9 270 top
TP26  TP  [TEST100]  51.56 37.08 270 top
U1  APL5930  [SOP127P600-9N]  68.35 85.78 90 top
U2  TMP431ADGKR  [TSOP65P490-8N]  26.72 24.62 180 top
U3  U_GPU_GB2C_64  [BGA90P27X27-595N]  39.18 47.3 90 top
U4  SN74AHC1G08  [SOT65P210-5N]  35.93 11.37 180 bottom
U36  MX25L3205D  [SOIC127P800-8N]  16.36 18.85 270 bottom
U37  APW7141  [PQFP50P365X365-14N]  12.99 34.51 180 bottom
U38  APL3526  [SON50P200X200-8N]  66.81 61.41 270 bottom
U39  APL3526  [SON50P200X200-8N]  61.16 53.3 180 bottom
U40  APW8805  [DFN50P300X300-10N]  69.28 72.63 270 top
U41  SN74AHC1G08  [SOT65P210-5N]  24.91 16.29 180 bottom
U43  SN74AHC1G08  [SOT65P210-5N]  23.01 13.51 180 bottom
U44  SN74AHC1G32  [SOT65P210-5N]  26.2 11.91 90 bottom
U46  SN74AHC1G08  [SOT65P210-5N]  9.79 25.37 270 bottom
X6  HSX321S  [OSC160P250X320_4N]  20.98 33.81 270 top

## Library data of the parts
C1 = C: signal model: DEFAULT_CAPACITOR_10000pF_2_1
C2 C10 C11 C14 C275 C338 C342 C344 C370 C536 C567 C568 C570 C571 C574 C620-C622 C634 C635 C684 C691 C743 C744 C849-C851 C855 C856 C858 C859 C862 C866 C874 C878 C888 C889 C893 C901 C903 C912 C917 C918 C920 C922 C925 C929 C931 C933 = C#1_0: tolerance: 10%
C3-C6 C8 C12 C13 C15-C18 C20-C24 C539-C543 C553-C562 C572 C573 C575-C588 C596-C600 C602-C607 C619 C623-C625 C628-C633 C637 C638 C647 C670 C672 C681-C683 C707 C710 C715 C726 C729 C741 C742 C748 C749 C758 C759 C761 C764-C766 C769 C783 C789 C809-C848 C860 C863 C867-C873 C882-C887 C890 C891 C894 C900 C910 C913-C916 C926 GC2 GC315-GC317 = C
C7 C276 C298 C471 C472 C537 C852 C857 C875 = C#1_0: alternate symbols: (T:CC0603N;B:CC0603M); tolerance: 20%
C9 = C: signal model: C_CC0402N_100NF_100nF
C19 C861 C899 C909 GC1 = C: alternate symbols: (T:CC0603N;B:CC0603M)
C310 C322 C473 C474 = C#1_0: tolerance: 20%
C326 C327 C475 C476 C923 C924 = C#1_0: alternate symbols: (T:CC0805N;B:CC0805M); tolerance: 15%
C330-C333 C478 C532-C534 = C: signal model: C_CC0402N_0.22UF_0.22uF
C569 C804 C805 C853 C854 C904 C921 = C#1_0: alternate symbols: (T:CC0805N;B:CC0805M); tolerance: 20%
C636 C692 C739 C745 C876 C881 C911 = C#1_0: alternate symbols: (T:CC0603N;B:CC0603M); tolerance: 10%
C864 C865 = C#1_0: tolerance: 5%
C877 C879 C880 C892 C919 C927 C928 C930 C932 GC3 = C_1: tolerance: 10%
C896 C898 = C: alternate symbols: (T:CC0805N;B:CC0805M)
CP1 CP3 CP4 CP10 CP11 CP13 = C_P: alternate symbols: (T:CCP7343N;B:CCP7343M)
CP12 PCP3 = C_P
D9 D12 = D
FB1 FB2 FB27 FB28 GFB11 = FB: alternate symbols: (T:FB0603N;B:FB0603M)
GCN1 = PCI-E_MINI_CARD_52
GCN2 GCN9 = CN4+2-S
GD10 = D: alternate symbols: (T:sod2514n;B:SOD2514M)
GQ2 = NPN-BEC+2R: alternate symbols: (T:SOT65P210-3N;B:SOT65P210-3M)
GR1-GR3 GR427-GR429 R4-R11 R13-R15 R18-R32 R37-R44 R100 R153 R154 R171 R176-R178 R180 R181 R187 R198 R200 R201 R240 R241 R246-R248 R250 R251 R257 R391 R392 R479-R481 R485 R486 R505 R507 R514 R515 R528 R532 R533 R556 R566 R570 R587-R589 R592-R599 R601 R603 R604 R642 R646 R647 R652 R654-R658 R670 R676 R679 R687 R688 R695 R697 R700 R703 R712 R735-R737 R742 R744 R755 R1722 = R
GR4 R179 R661 R691 R696 R698 R699 R701 R702 = R: alternate symbols: (T:RC0603N;B:RC0603M)
GR5 GR8 GR11 GR13 R16 R17 R750-R754 = R_0
GR6 = R_1: tolerance: 5 %
GR9 R614 R615 R740 R745-R749 = R#1_1: tolerance: 1 %
GU1 = 24+1_RT8813A_0
L1 L8-L10 = L
L11 = L_1: tolerance: 20%
M1 M4 = 170_K4G41325FC
M2 M3 = 170_K4G41325FC-M
MARK1-MARK8 = MARK
MH1-MH11 = H
Q1 = NPN-BEC: alternate symbols: (T:SOT95P230-3N;B:SOT95P230-3M)
Q2 Q4 Q6 Q7 Q25 Q30 Q33-Q36 = NMOS-GSD: alternate symbols: (T:SOT95P280-3N;B:SOT95P280-3M)
Q37-Q42 Q44 Q54 = PWR_N_MOSFET
Q55 Q70-Q72 Q75 Q76 = NMOS-GSD
R1 = R: signal model: DEFAULT_RESISTOR_100000OHM_2_1
R2 R3 = R: alternate symbols: (T:RC0805N;B:RC0805M)
R12 R650 R659 R734 R738 R739 R741 R743 R757 = R#1_1: tolerance: 5 %
R33-R36 R45 R618 R756 = R#1_1: tolerance: 0.05 ohm
R194 R197 = R_1: tolerance: 1 %
R252 R259 R482 R704-R706 = R_1: tolerance: 0.05 ohm
R483 R516 R517 R648 R649 R651 R665 R666 R677 = R_1: tolerance: ?
R600 R602 R605 R606 R617 R634-R640 R643-R645 = R#1_1: tolerance: 5%
R619 R622 R631 R641 = R#1_1: tolerance: ?
R664 = R_0: alternate symbols: (T:RC0603N;B:RC0603M)
TP1 TP9 TP15 TP19 TP24 TP26 = TP
U1 = APL591X_1
U2 = 8_EMC1402
U3 = 595_U_GPU_GB2C_64
U4 U41 U43 U44 U46 = 5_SN74AHC1G09DCK
U36 = 8_MX25L4005AMC-12G
U37 = 14+1_tps51117RGY_2
U38 U39 = 8+1_TPS22965
U40 = 10+1_APW8805_0
X6 = OSC-4_1

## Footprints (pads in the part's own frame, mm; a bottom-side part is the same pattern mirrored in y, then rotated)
BGA80P14X17-170N-A
  round 0.45 smd: A1(-5.2,6.4) A2(-4.4,6.4) A3(-3.6,6.4) A4(-2.8,6.4) A5(-2,6.4) A10(2,6.4) A11(2.8,6.4) A12(3.6,6.4) A13(4.4,6.4) A14(5.2,6.4) B1(-5.2,5.6) B2(-4.4,5.6) B3(-3.6,5.6) B4(-2.8,5.6) B5(-2,5.6) B10(2,5.6) B11(2.8,5.6) B12(3.6,5.6) B13(4.4,5.6) B14(5.2,5.6) C1(-5.2,4.8) C2(-4.4,4.8) C3(-3.6,4.8) C4(-2.8,4.8) C5(-2,4.8) C10(2,4.8) C11(2.8,4.8) C12(3.6,4.8) C13(4.4,4.8) C14(5.2,4.8) D1(-5.2,4) D2(-4.4,4) D3(-3.6,4) D4(-2.8,4) D5(-2,4) D10(2,4) D11(2.8,4) D12(3.6,4) D13(4.4,4) D14(5.2,4) E1(-5.2,3.2) E2(-4.4,3.2) E3(-3.6,3.2) E4(-2.8,3.2) E5(-2,3.2) E10(2,3.2) E11(2.8,3.2) E12(3.6,3.2) E13(4.4,3.2) E14(5.2,3.2) F1(-5.2,2.4) F2(-4.4,2.4) F3(-3.6,2.4) F4(-2.8,2.4) F5(-2,2.4) F10(2,2.4) F11(2.8,2.4) F12(3.6,2.4) F13(4.4,2.4) F14(5.2,2.4) G1(-5.2,1.6) G2(-4.4,1.6) G3(-3.6,1.6) G4(-2.8,1.6) G5(-2,1.6) G10(2,1.6) G11(2.8,1.6) G12(3.6,1.6) G13(4.4,1.6) G14(5.2,1.6) H1(-5.2,0.8) H2(-4.4,0.8) H3(-3.6,0.8) H4(-2.8,0.8) H5(-2,0.8) H10(2,0.8) H11(2.8,0.8) H12(3.6,0.8) H13(4.4,0.8) H14(5.2,0.8) J1(-5.2,0) J2(-4.4,0) J3(-3.6,0) J4(-2.8,0) J5(-2,0) J10(2,0) J11(2.8,0) J12(3.6,0) J13(4.4,0) J14(5.2,0) K1(-5.2,-0.8) K2(-4.4,-0.8) K3(-3.6,-0.8) K4(-2.8,-0.8) K5(-2,-0.8) K10(2,-0.8) K11(2.8,-0.8) K12(3.6,-0.8) K13(4.4,-0.8) K14(5.2,-0.8) L1(-5.2,-1.6) L2(-4.4,-1.6) L3(-3.6,-1.6) L4(-2.8,-1.6) L5(-2,-1.6) L10(2,-1.6) L11(2.8,-1.6) L12(3.6,-1.6) L13(4.4,-1.6) L14(5.2,-1.6) M1(-5.2,-2.4) M2(-4.4,-2.4) M3(-3.6,-2.4) M4(-2.8,-2.4) M5(-2,-2.4) M10(2,-2.4) M11(2.8,-2.4) M12(3.6,-2.4) M13(4.4,-2.4) M14(5.2,-2.4) N1(-5.2,-3.2) N2(-4.4,-3.2) N3(-3.6,-3.2) N4(-2.8,-3.2) N5(-2,-3.2) N10(2,-3.2) N11(2.8,-3.2) N12(3.6,-3.2) N13(4.4,-3.2) N14(5.2,-3.2) P1(-5.2,-4) P2(-4.4,-4) P3(-3.6,-4) P4(-2.8,-4) P5(-2,-4) P10(2,-4) P11(2.8,-4) P12(3.6,-4) P13(4.4,-4) P14(5.2,-4) R1(-5.2,-4.8) R2(-4.4,-4.8) R3(-3.6,-4.8) R4(-2.8,-4.8) R5(-2,-4.8) R10(2,-4.8) R11(2.8,-4.8) R12(3.6,-4.8) R13(4.4,-4.8) R14(5.2,-4.8) T1(-5.2,-5.6) T2(-4.4,-5.6) T3(-3.6,-5.6) T4(-2.8,-5.6) T5(-2,-5.6) T10(2,-5.6) T11(2.8,-5.6) T12(3.6,-5.6) T13(4.4,-5.6) T14(5.2,-5.6) V1(-5.2,-6.4) V2(-4.4,-6.4) V3(-3.6,-6.4) V4(-2.8,-6.4) V5(-2,-6.4) V10(2,-6.4) V11(2.8,-6.4) V12(3.6,-6.4) V13(4.4,-6.4) V14(5.2,-6.4)
BGA90P27X27-595N
  round 0.38 smd: A2(-9.9,10.7) A3(-9.1,10.7) A4(-8.3,10.7) A6(-6.6,10.7) A7(-5.8,10.7) A9(-4.12,10.7) A10(-3.32,10.7) A12(-1.64,10.7) A13(-0.84,10.7) A15(0.84,10.7) A16(1.64,10.7) A18(3.32,10.7) A19(4.12,10.7) A21(5.8,10.7) A22(6.6,10.7) A24(8.3,10.7) A25(9.1,10.7) A26(9.9,10.7) AA1(-10.7,-5.8) AA2(-9.9,-5.8) AA3(-9.1,-5.8) AA4(-8.3,-5.8) AA5(-7.5,-5.8) AA6(-6.66,-5.8) AA7(-5.8,-5.8) AA8(-4.96,-5.8) AA9(-4.12,-5.86) AA10(-3.32,-5.86) AA12(-1.64,-5.86) AA13(-0.84,-5.86) AA14(0,-5.86) AA15(0.84,-5.86) AA16(1.64,-5.86) AA18(3.32,-5.86) AA19(4.12,-5.86) AA20(4.96,-5.8) AA21(5.8,-5.8) AA22(6.66,-5.8) AA23(7.5,-5.8) AA24(8.3,-5.8) AA25(9.1,-5.8) AA26(9.9,-5.8) AA27(10.7,-5.8) AB1(-10.7,-6.6) AB2(-9.9,-6.6) AB3(-9.1,-6.6) AB4(-8.3,-6.6) AB5(-7.5,-6.6) AB6(-6.6,-6.6) AB7(-5.8,-6.66) AB8(-4.96,-6.66) AB9(-4.12,-6.66) AB10(-3.32,-6.66) AB11(-2.48,-6.66) AB12(-1.64,-6.66) AB13(-0.84,-6.66) AB14(0,-6.66) AB15(0.84,-6.66) AB16(1.64,-6.66) AB17(2.48,-6.66) AB18(3.32,-6.66) AB19(4.12,-6.66) AB20(4.96,-6.66) AB21(5.8,-6.66) AB22(6.6,-6.6) AB23(7.5,-6.6) AB24(8.3,-6.6) AB25(9.1,-6.6) AB26(9.9,-6.6) AB27(10.7,-6.6) AC2(-9.9,-7.45) AC3(-9.1,-7.45) AC4(-8.3,-7.45) AC5(-7.45,-7.45) AC6(-6.6,-7.5) AC7(-5.8,-7.5) AC8(-4.96,-7.5) AC9(-4.12,-7.5) AC10(-3.32,-7.5) AC11(-2.48,-7.5) AC12(-1.64,-7.5) AC13(-0.84,-7.5) AC14(0,-7.5) AC15(0.84,-7.5) AC16(1.64,-7.5) AC17(2.48,-7.5) AC18(3.32,-7.5) AC19(4.12,-7.5) AC20(4.96,-7.5) AC21(5.8,-7.5) AC22(6.6,-7.5) AC23(7.45,-7.45) AC24(8.3,-7.45) AC25(9.1,-7.45) AC26(9.9,-7.45) AD1(-10.7,-8.3) AD2(-9.9,-8.3) AD3(-9.1,-8.3) AD4(-8.3,-8.3) AD5(-7.45,-8.3) AD6(-6.6,-8.3) AD7(-5.8,-8.3) AD8(-4.96,-8.3) AD9(-4.12,-8.3) AD10(-3.32,-8.3) AD11(-2.48,-8.3) AD12(-1.64,-8.3) AD13(-0.84,-8.3) AD14(0,-8.3) AD15(0.84,-8.3) AD16(1.64,-8.3) AD17(2.48,-8.3) AD18(3.32,-8.3) AD19(4.12,-8.3) AD20(4.96,-8.3) AD21(5.8,-8.3) AD22(6.6,-8.3) AD23(7.45,-8.3) AD24(8.3,-8.3) AD25(9.1,-8.3) AD26(9.9,-8.3) AD27(10.7,-8.3) AE1(-10.7,-9.1) AE2(-9.9,-9.1) AE3(-9.1,-9.1) AE4(-8.3,-9.1) AE5(-7.45,-9.1) AE6(-6.6,-9.1) AE7(-5.8,-9.1) AE8(-4.96,-9.1) AE9(-4.12,-9.1) AE10(-3.32,-9.1) AE11(-2.48,-9.1) AE12(-1.64,-9.1) AE13(-0.84,-9.1) AE14(0,-9.1) AE15(0.84,-9.1) AE16(1.64,-9.1) AE17(2.48,-9.1) AE18(3.32,-9.1) AE19(4.12,-9.1) AE20(4.96,-9.1) AE21(5.8,-9.1) AE22(6.6,-9.1) AE23(7.45,-9.1) AE24(8.3,-9.1) AE25(9.1,-9.1) AE26(9.9,-9.1) AE27(10.7,-9.1) AF1(-10.7,-9.9) AF2(-9.9,-9.9) AF3(-9.1,-9.9) AF4(-8.3,-9.9) AF5(-7.45,-9.9) AF6(-6.6,-9.9) AF7(-5.8,-9.9) AF8(-4.96,-9.9) AF9(-4.12,-9.9) AF10(-3.32,-9.9) AF11(-2.48,-9.9) AF12(-1.64,-9.9) AF13(-0.84,-9.9) AF14(0,-9.9) AF15(0.84,-9.9) AF16(1.64,-9.9) AF17(2.48,-9.9) AF18(3.32,-9.9) AF19(4.12,-9.9) AF20(4.96,-9.9) AF21(5.8,-9.9) AF22(6.6,-9.9) AF23(7.45,-9.9) AF24(8.3,-9.9) AF25(9.1,-9.9) AF26(9.9,-9.9) AF27(10.7,-9.9) AG2(-9.9,-10.7) AG3(-9.1,-10.7) AG4(-8.3,-10.7) AG6(-6.6,-10.7) AG7(-5.8,-10.7) AG9(-4.12,-10.7) AG10(-3.32,-10.7) AG12(-1.64,-10.7) AG13(-0.84,-10.7) AG15(0.84,-10.7) AG16(1.64,-10.7) AG18(3.32,-10.7) AG19(4.12,-10.7) AG21(5.8,-10.7) AG22(6.6,-10.7) AG24(8.3,-10.7) AG25(9.1,-10.7) AG26(9.9,-10.7) B1(-10.7,9.9) B2(-9.9,9.9) B3(-9.1,9.9) B4(-8.3,9.9) B5(-7.45,9.9) B6(-6.6,9.9) B7(-5.8,9.9) B8(-4.96,9.9) B9(-4.12,9.9) B10(-3.32,9.9) B11(-2.48,9.9) B12(-1.64,9.9) B13(-0.84,9.9) B14(0,9.9) B15(0.84,9.9) B16(1.64,9.9) B17(2.48,9.9) B18(3.32,9.9) B19(4.12,9.9) B20(4.96,9.9) B21(5.8,9.9) B22(6.6,9.9) B23(7.45,9.9) B24(8.3,9.9) B25(9.1,9.9) B26(9.9,9.9) B27(10.7,9.9) C1(-10.7,9.1) C2(-9.9,9.1) C3(-9.1,9.1) C4(-8.3,9.1) C5(-7.45,9.1) C6(-6.6,9.1) C7(-5.8,9.1) C8(-4.96,9.1) C9(-4.12,9.1) C10(-3.32,9.1) C11(-2.48,9.1) C12(-1.64,9.1) C13(-0.84,9.1) C14(0,9.1) C15(0.84,9.1) C16(1.64,9.1) C17(2.48,9.1) C18(3.32,9.1) C19(4.12,9.1) C20(4.96,9.1) C21(5.8,9.1) C22(6.6,9.1) C23(7.45,9.1) C24(8.3,9.1) C25(9.1,9.1) C26(9.9,9.1) C27(10.7,9.1) D1(-10.7,8.3) D2(-9.9,8.3) D3(-9.1,8.3) D4(-8.3,8.3) D5(-7.45,8.3) D6(-6.6,8.3) D7(-5.8,8.3) D8(-4.96,8.3) D9(-4.12,8.3) D10(-3.32,8.3) D11(-2.48,8.3) D12(-1.64,8.3) D13(-0.84,8.3) D14(0,8.3) D15(0.84,8.3) D16(1.64,8.3) D17(2.48,8.3) D18(3.32,8.3) D19(4.12,8.3) D20(4.96,8.3) D21(5.8,8.3) D22(6.6,8.3) D23(7.45,8.3) D24(8.3,8.3) D25(9.1,8.3) D26(9.9,8.3) D27(10.7,8.3) E2(-9.9,7.45) E3(-9.1,7.45) E4(-8.3,7.45) E5(-7.45,7.45) E6(-6.6,7.5) E7(-5.8,7.5) E8(-4.96,7.5) E9(-4.12,7.5) E10(-3.32,7.5) E11(-2.48,7.5) E12(-1.64,7.5) E13(-0.84,7.5) E14(0,7.5) E15(0.84,7.5) E16(1.64,7.5) E17(2.48,7.5) E18(3.32,7.5) E19(4.12,7.5) E20(4.96,7.5) E21(5.8,7.5) E22(6.6,7.5) E23(7.45,7.45) E24(8.3,7.45) E25(9.1,7.45) E26(9.9,7.45) F1(-10.7,6.6) F2(-9.9,6.6) F3(-9.1,6.6) F4(-8.3,6.6) F5(-7.5,6.6) F6(-6.6,6.6) F7(-5.8,6.66) F8(-4.96,6.66) F9(-4.12,6.66) F10(-3.32,6.66) F11(-2.48,6.66) F12(-1.64,6.66) F13(-0.84,6.66) F14(0,6.66) F15(0.84,6.66) F16(1.64,6.66) F17(2.48,6.66) F18(3.32,6.66) F19(4.12,6.66) F20(4.96,6.66) F21(5.8,6.66) F22(6.6,6.6) F23(7.5,6.6) F24(8.3,6.6) F25(9.1,6.6) F26(9.9,6.6) F27(10.7,6.6) G1(-10.7,5.8) G2(-9.9,5.8) G3(-9.1,5.8) G4(-8.3,5.8) G5(-7.5,5.8) G6(-6.66,5.8) G7(-5.8,5.8) G8(-4.96,5.8) G9(-4.12,5.86) G10(-3.32,5.86) G12(-1.64,5.86) G13(-0.84,5.86) G14(0,5.86) G15(0.84,5.86) G16(1.64,5.86) G18(3.32,5.86) G19(4.12,5.86) G20(4.96,5.8) G21(5.8,5.8) G22(6.66,5.8) G23(7.5,5.8) G24(8.3,5.8) G25(9.1,5.8) G26(9.9,5.8) G27(10.7,5.8) H2(-9.9,4.96) H3(-9.1,4.96) H4(-8.3,4.96) H5(-7.5,4.96) H6(-6.66,4.96) H22(6.66,4.96) H23(7.5,4.96) H24(8.3,4.96) H25(9.1,4.96) H26(9.9,4.96) J1(-10.7,4.12) J2(-9.9,4.12) J3(-9.1,4.12) J4(-8.3,4.12) J5(-7.5,4.12) J6(-6.66,4.12) J7(-5.86,4.12) J21(5.86,4.12) J22(6.66,4.12) J23(7.5,4.12) J24(8.3,4.12) J25(9.1,4.12) J26(9.9,4.12) J27(10.7,4.12) K1(-10.7,3.32) K2(-9.9,3.32) K3(-9.1,3.32) K4(-8.3,3.32) K5(-7.5,3.32) K6(-6.66,3.32) K7(-5.86,3.32) K21(5.86,3.32) K22(6.66,3.32) K23(7.5,3.32) K24(8.3,3.32) K25(9.1,3.32) K26(9.9,3.32) K27(10.7,3.32) L2(-9.9,2.48) L3(-9.1,2.48) L4(-8.3,2.48) L5(-7.5,2.48) L6(-6.66,2.48) L22(6.66,2.48) L23(7.5,2.48) L24(8.3,2.48) L25(9.1,2.48) L26(9.9,2.48) M1(-10.7,1.64) M2(-9.9,1.64) M3(-9.1,1.64) M4(-8.3,1.64) M5(-7.5,1.64) M6(-6.66,1.64) M7(-5.86,1.64) M21(5.86,1.64) M22(6.66,1.64) M23(7.5,1.64) M24(8.3,1.64) M25(9.1,1.64) M26(9.9,1.64) M27(10.7,1.64) N1(-10.7,0.84) N2(-9.9,0.84) N3(-9.1,0.84) N4(-8.3,0.84) N5(-7.5,0.84) N6(-6.66,0.84) N7(-5.86,0.84) N21(5.86,0.84) N22(6.66,0.84) N23(7.5,0.84) N24(8.3,0.84) N25(9.1,0.84) N26(9.9,0.84) N27(10.7,0.84) P2(-9.9,0) P3(-9.1,0) P4(-8.3,0) P5(-7.5,0) P6(-6.66,0) P22(6.66,0) P23(7.5,0) P24(8.3,0) P25(9.1,0) P26(9.9,0) R1(-10.7,-0.84) R2(-9.9,-0.84) R3(-9.1,-0.84) R4(-8.3,-0.84) R5(-7.5,-0.84) R6(-6.66,-0.84) R7(-5.86,-0.84) R21(5.86,-0.84) R22(6.66,-0.84) R23(7.5,-0.84) R24(8.3,-0.84) R25(9.1,-0.84) R26(9.9,-0.84) R27(10.7,-0.84) T1(-10.7,-1.64) T2(-9.9,-1.64) T3(-9.1,-1.64) T4(-8.3,-1.64) T5(-7.5,-1.64) T6(-6.66,-1.64) T7(-5.86,-1.64) T21(5.86,-1.64) T22(6.66,-1.64) T23(7.5,-1.64) T24(8.3,-1.64) T25(9.1,-1.64) T26(9.9,-1.64) T27(10.7,-1.64) U2(-9.9,-2.48) U3(-9.1,-2.48) U4(-8.3,-2.48) U5(-7.5,-2.48) U6(-6.66,-2.48) U22(6.66,-2.48) U23(7.5,-2.48) U24(8.3,-2.48) U25(9.1,-2.48) U26(9.9,-2.48) V1(-10.7,-3.32) V2(-9.9,-3.32) V3(-9.1,-3.32) V4(-8.3,-3.32) V5(-7.5,-3.32) V6(-6.66,-3.32) V7(-5.86,-3.32) V21(5.86,-3.32) V22(6.66,-3.32) V23(7.5,-3.32) V24(8.3,-3.32) V25(9.1,-3.32) V26(9.9,-3.32) V27(10.7,-3.32) W1(-10.7,-4.12) W2(-9.9,-4.12) W3(-9.1,-4.12) W4(-8.3,-4.12) W5(-7.5,-4.12) W6(-6.66,-4.12) W7(-5.86,-4.12) W21(5.86,-4.12) W22(6.66,-4.12) W23(7.5,-4.12) W24(8.3,-4.12) W25(9.1,-4.12) W26(9.9,-4.12) W27(10.7,-4.12) Y2(-9.9,-4.96) Y3(-9.1,-4.96) Y4(-8.3,-4.96) Y5(-7.5,-4.96) Y6(-6.66,-4.96) Y22(6.66,-4.96) Y23(7.5,-4.96) Y24(8.3,-4.96) Y25(9.1,-4.96) Y26(9.9,-4.96)
  round 0.4 smd: K10(-4,4) K11(-3,4) K12(-2,4) K13(-1,4) K14(0,4) K15(1,4) K16(2,4) K17(3,4) K18(4,4) L10(-4,3) L11(-3,3) L12(-2,3) L13(-1,3) L14(0,3) L15(1,3) L16(2,3) L17(3,3) L18(4,3) M10(-4,2) M11(-3,2) M12(-2,2) M13(-1,2) M14(0,2) M15(1,2) M16(2,2) M17(3,2) M18(4,2) N10(-4,1) N11(-3,1) N12(-2,1) N13(-1,1) N14(0,1) N15(1,1) N16(2,1) N17(3,1) N18(4,1) P10(-4,0) P11(-3,0) P12(-2,0) P13(-1,0) P14(0,0) P15(1,0) P16(2,0) P17(3,0) P18(4,0) R10(-4,-1) R11(-3,-1) R12(-2,-1) R13(-1,-1) R14(0,-1) R15(1,-1) R16(2,-1) R17(3,-1) R18(4,-1) T10(-4,-2) T11(-3,-2) T12(-2,-2) T13(-1,-2) T14(0,-2) T15(1,-2) T16(2,-2) T17(3,-2) T18(4,-2) U10(-4,-3) U11(-3,-3) U12(-2,-3) U13(-1,-3) U14(0,-3) U15(1,-3) U16(2,-3) U17(3,-3) U18(4,-3) V10(-4,-4) V11(-3,-4) V12(-2,-4) V13(-1,-4) V14(0,-4) V15(1,-4) V16(2,-4) V17(3,-4) V18(4,-4)
CAE660W800HN
  rect 3.35x1.6 smd: 1(-2.45,0) 2(2.45,0)
CC0402N
  rect 0.55x0.5 smd: 1(-0.475,0) 2(0.475,0)
CC0603N
  rect 0.8x0.8 smd: 1(-0.75,0) 2(0.75,0)
CC0805N
  rect 1x1.2 smd: 1(-1,0) 2(1,0)
CCP7343N
  rect 2.6x2.6 smd: 1(-3.05,0) 2(3.05,0)
DFN50P300X300-10N
  oval 0.8x0.28 smd: 1(-1.5,1) 2(-1.5,0.5) 3(-1.5,0) 4(-1.5,-0.5) 5(-1.5,-1) 6(1.5,-1) 7(1.5,-0.5) 8(1.5,0) 9(1.5,0.5) 10(1.5,1)
  rect 1.75x2.7 smd: E1(0,0)
FB0603N
  rect 0.8x0.8 smd: 1(-0.75,0) 2(0.75,0)
FINGER-PCIE-80P-52N
  rect 0.6x2.3 smd: 1(7.95,0) 2(7.55,0) 3(7.15,0) 4(6.75,0) 5(6.35,0) 6(5.95,0) 7(5.55,0) 8(5.15,0) 9(4.75,0) 10(4.35,0) 11(3.95,0) 12(3.55,0) 13(3.15,0) 14(2.75,0) 15(2.35,0) 16(1.95,0) 17(-1.65,0) 18(-2.05,0) 19(-2.45,0) 20(-2.85,0) 21(-3.25,0) 22(-3.65,0) 23(-4.05,0) 24(-4.45,0) 25(-4.85,0) 26(-5.25,0) 27(-5.65,0) 28(-6.05,0) 29(-6.45,0) 30(-6.85,0) 31(-7.25,0) 32(-7.65,0) 33(-8.05,0) 34(-8.45,0) 35(-8.85,0) 36(-9.25,0) 37(-9.65,0) 38(-10.05,0) 39(-10.45,0) 40(-10.85,0) 41(-11.25,0) 42(-11.65,0) 43(-12.05,0) 44(-12.45,0) 45(-12.85,0) 46(-13.25,0) 47(-13.65,0) 48(-14.05,0) 49(-14.45,0) 50(-14.85,0) 51(-15.25,0) 52(-15.65,0)
L600P-686X647-2N
  rect 2x3.5 smd: 1(-3,0) 2(3,0)
LC6666N
  rect 2.3x3.3 smd: 1(-3.075,0) 2(3.075,0)
LC7266N
  rect 3.5x2.6 smd: 1(0,3.15) 2(0,-3.15)
MARK-D100D250
  round 1 smd: 1(0,0)
MTG230H500
  round 5 hole 2.3: 1(0,0)
MTG340H600
  round 6 hole 3.4: 1(0,0)
OSC160P250X320_4N
  rect 1.3x1 smd: 1(-1.05,-0.8) 2(1.05,-0.8) 3(1.05,0.8) 4(-1.05,0.8)
PQFP50P365X365-14N
  oval 0.7x0.28 smd: 1(-1.775,-0.75) 7(1.775,-0.75) 8(1.775,0.75) 14(-1.775,0.75)
  oval 0.28x0.7 smd: 2(-1,-1.775) 3(-0.5,-1.775) 4(0,-1.775) 5(0.5,-1.775) 6(1,-1.775) 9(1,1.775) 10(0.5,1.775) 11(0,1.775) 12(-0.5,1.775) 13(-1,1.775)
  rect 2.05x2.05 smd: E1(0,0)
QFN50P400X400-24AN
  oval 0.8x0.28 smd: 1(-2,1.25) 2(-2,0.75) 3(-2,0.25) 4(-2,-0.25) 5(-2,-0.75) 6(-2,-1.25) 13(2,-1.25) 14(2,-0.75) 15(2,-0.25) 16(2,0.25) 17(2,0.75) 18(2,1.25)
  oval 0.28x0.8 smd: 7(-1.25,-2) 8(-0.75,-2) 9(-0.25,-2) 10(0.25,-2) 11(0.75,-2) 12(1.25,-2) 19(1.25,2) 20(0.75,2) 21(0.25,2) 22(-0.25,2) 23(-0.75,2) 24(-1.25,2)
  rect 2.25x2.25 smd: E1(0,0)
RC0402N
  rect 0.55x0.5 smd: 1(-0.475,0) 2(0.475,0)
RC0603N
  rect 0.8x0.8 smd: 1(-0.75,0) 2(0.75,0)
RC0805N
  rect 1x1.2 smd: 1(-1,0) 2(1,0)
SMD-CN-100P-4N-V-CB
  rect 0.6x1.5 smd: 1(1.5,2.55) 2(0.5,2.55) 3(-0.5,2.55) 4(-1.5,2.55)
  rect 1.2x1.8 smd: E1(-2.8,0) E2(2.8,0)
SMD-CN-125P-4BN
  rect 0.5x1.5 smd: 1(1.875,-1.8) 2(0.625,-1.8) 3(-0.625,-1.8) 4(-1.875,-1.8)
  rect 2.4x2.5 smd: E1(-4.625,0) E2(4.625,0)
SOD1006BN
  rect 0.4x0.4 smd: N(0.4,0) P(-0.4,0)
SOD1713N
  rect 0.8x0.6 smd: N(1.25,0) P(-1.25,0)
SOD2514N
  rect 1.2x0.5 smd: N(-1.15,0) P(1.15,0)
SOIC127P605X520-8N
  rect 0.7x0.5 smd: 1(-2.825,1.905) 2(-2.825,0.635) 3(-2.825,-0.635) 4(-2.825,-1.905) 5(2.825,-1.905) 6(2.825,-0.635) 7(2.825,0.635)
  custom 1.12x1.12 smd: 8(0.7,0)
SOIC127P800-8N
  rect 1.8x0.6 smd: 1(-3.6,1.905) 2(-3.6,0.635) 3(-3.6,-0.635) 4(-3.6,-1.905) 5(3.6,-1.905) 6(3.6,-0.635) 7(3.6,0.635) 8(3.6,1.905)
SON50P200X200-8N
  oval 0.6x0.25 smd: 1(-1,0.749) 2(-1,0.249) 3(-1,-0.251) 4(-1,-0.751) 5(1,-0.751) 6(1,-0.251) 7(1,0.249) 8(1,0.749)
  rect 0.9x1.6 smd: E1(0,0)
SOP127P600-9N
  rect 1.9x0.6 smd: 1(-2.55,1.905) 2(-2.55,0.635) 3(-2.55,-0.635) 4(-2.55,-1.905) 5(2.55,-1.905) 6(2.55,-0.635) 7(2.55,0.635) 8(2.55,1.905)
  rect 2.6x3 smd: E1(0,0)
SOT65P210-3N
  rect 1.2x0.45 smd: 1(-0.9,0.65) 2(-0.9,-0.65) 3(0.9,0)
SOT65P210-5N
  rect 1.1x0.4 smd: 1(-0.95,0.65) 2(-0.95,0) 3(-0.95,-0.65) 4(0.95,-0.65) 5(0.95,0.65)
SOT95P230-3N
  rect 1.25x0.6 smd: 1(-1.05,0.95) 2(-1.05,-0.95) 3(1.05,0)
SOT95P240-3N
  rect 1.4x0.6 smd: 1(-1,0.95) 2(-1,-0.95) 3(1,0)
SOT95P280-3N
  rect 1.35x0.6 smd: 1(-1.25,0.95) 2(-1.25,-0.95) 3(1.25,0)
TEST100
  round 1 smd: 1(0,0)
TSOP65P490-8N
  rect 1.45x0.4 smd: 1(-2.2,0.975) 2(-2.2,0.325) 3(-2.2,-0.325) 4(-2.2,-0.975) 5(2.2,-0.975) 6(2.2,-0.325) 7(2.2,0.325) 8(2.2,0.975)
unnamed
  round 2 hole 2 unplated: (0,0)

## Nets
5V_SW: C874.1 C875.1 C900.2 C915.2 C916.2 C920.1 C921.1 D12.P GR4.1 GU1.21(PVCC) R679.1 R696.2 R735.2 R747.1 R755.2 U37.10(V5DRV) U38.4(VBIAS) U39.4(VBIAS) U40.3(VIN)
+V1P8S: C12.1 C13.1 C15.1 R21.2 R712.1 U1.3(VOUT1) U1.4(VOUT2)
+V3.3S: C18.1 C21.2 C927.1 C928.1 C930.1 C932.1 GCN1.24(+3.3V_AUX) GCN1.52(+3.3V_2) GR427.1 R16.1 R17.2 R20.1 R22.2 R26.1 R27.2 R600.1 R644.1 R697.1 R734.1 R740.1 R749.1 U2.1(VDD) U4.5(VCC) U41.5(VCC) U43.5(VCC) U44.5(VCC) U46.5(VCC)
+V5S: C17.1 GCN1.8(UIM_PWR1) GFB11.2 GR2.1 GR3.1 GR428.1 R735.1 U1.6(VCNTL)
